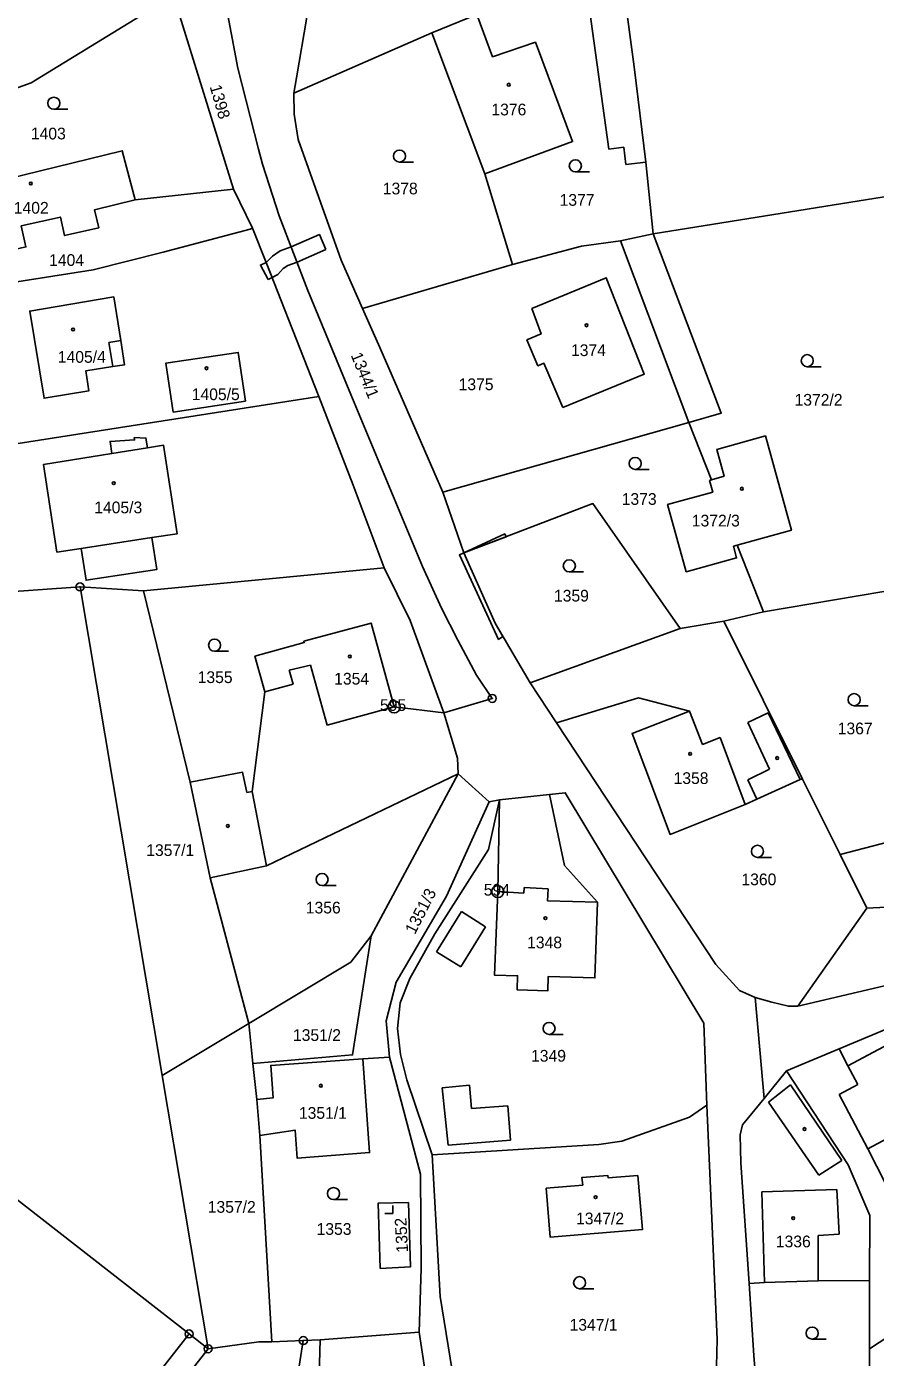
# Model space of a CAD drawing. Extents: x -587171 to -555306, y -1167727 to -1074732.
# Drawn here: x -559852.9 to -559747.3, y -1076385.1 to -1076219.5 of the extents above; entities that cross this region are included whole.
import ezdxf

# ---------------------------------------------------------------- set-up
doc = ezdxf.new("R2010")
doc.units = 0
for name, color, linetype in [('Hranice parcel', 7, 'Continuous'), ('Parcelní čísla', 7, 'Continuous'), ('Vnitřní kresba', 7, 'Continuous'), ('Věcná břemena k části', 7, 'Continuous'), ('Značky bodu BP', 7, 'Continuous'), ('Značky budov', 7, 'Continuous'), ('Značky kultur', 7, 'Continuous')]:
    doc.layers.add(name, color=color, linetype=linetype)

msp = doc.modelspace()

# ---------------------------------------------------------------- linework, layer by layer
at = {"layer": 'Hranice parcel'}
for p, q in [((-559834.6, -1076215.6), (-559827.15, -1076239.74)), ((-559796.86, -1076218), (-559802.48, -1076220.25)), ((-559802.48, -1076220.25), (-559819.62, -1076227.79)), ((-559802.48, -1076220.25), (-559795.86, -1076237.82)), ((-559795.86, -1076237.82), (-559792.44, -1076249.08)), ((-559839.38, -1076241.05), (-559827.15, -1076239.74)), ((-559827.15, -1076239.74), (-559824.78, -1076244.58)), ((-559746.19, -1076240.66), (-559774.92, -1076245.29)), ((-559792.44, -1076249.08), (-559811.08, -1076254.57)), ((-559917.53, -1076281.27), (-559816.53, -1076265.53)), ((-559770.49, -1076268.74), (-559801.09, -1076277.4)), ((-559767.68, -1076275.89), (-559770.49, -1076268.74)), ((-559801.09, -1076277.4), (-559798.5, -1076284.98)), ((-559761.21, -1076292.32), (-559764.48, -1076284.02)), ((-559808.4, -1076286.82), (-559838.33, -1076289.68)), ((-559838.33, -1076289.68), (-559846.23, -1076289.21)), ((-559836.01, -1076350.01), (-559846.23, -1076289.21)), ((-559838.33, -1076289.68), (-559832.53, -1076313.51)), ((-559742.81, -1076289.2), (-559761.21, -1076292.32)), ((-559766.15, -1076293.47), (-559771.58, -1076294.37)), ((-559761.21, -1076292.32), (-559766.15, -1076293.47)), ((-559756.34, -1076313.12), (-559766.15, -1076293.47)), ((-559771.58, -1076294.37), (-559790.22, -1076301.15)), ((-559790.22, -1076301.15), (-559786.94, -1076306.13)), ((-559810.01, -1076332.61), (-559799.17, -1076312.48)), ((-559799.17, -1076312.48), (-559795.34, -1076315.97)), ((-559751.67, -1076322.49), (-559756.34, -1076313.12)), ((-559832.53, -1076313.51), (-559830.02, -1076325.39)), ((-559787.84, -1076315.03), (-559794.04, -1076315.72)), ((-559795.34, -1076315.97), (-559794.04, -1076315.72)), ((-559732.13, -1076317.38), (-559751.67, -1076322.49)), ((-559748.34, -1076329.2), (-559751.67, -1076322.49)), ((-559830.02, -1076325.39), (-559825.24, -1076343.53)), ((-559725.3, -1076327.83), (-559748.34, -1076329.2)), ((-559756.94, -1076341.36), (-559748.34, -1076329.2)), ((-559762.25, -1076340.3), (-559761.13, -1076352.85)), ((-559836.01, -1076350.01), (-559825.24, -1076343.53)), ((-559824.71, -1076348.5), (-559825.24, -1076343.53)), ((-559807.72, -1076347.73), (-559811.03, -1076347.93)), ((-559751.79, -1076346.69), (-559758.34, -1076349.44)), ((-559824.24, -1076353), (-559824.71, -1076348.5)), ((-559758.34, -1076349.44), (-559761.13, -1076352.85)), ((-559830.29, -1076384), (-559836.01, -1076350.01)), ((-559823.85, -1076357.47), (-559824.24, -1076353)), ((-559823.85, -1076357.47), (-559822.35, -1076383.15)), ((-559748.01, -1076375.52), (-559748.02, -1076384.02)), ((-559832.66, -1076382.16), (-559859.22, -1076415.94)), ((-559832.66, -1076382.16), (-559830.29, -1076384)), ((-559824.03, -1076417.57), (-559818.45, -1076382.98)), ((-559822.35, -1076383.15), (-559818.45, -1076382.98)), ((-559818.45, -1076382.98), (-559816.37, -1076382.89)), ((-559816.37, -1076382.89), (-559817.26, -1076419.52)), ((-559816.37, -1076382.89), (-559804.04, -1076381.95)), ((-559850.66, -1076409.89), (-559830.29, -1076384)), ((-559748.02, -1076384.02), (-559748.03, -1076392.42))]:
    msp.add_line(p, q, dxfattribs=at)
for points in [[(-559800.97, -1076304.86), (-559794.95, -1076303.08), (-559796.9, -1076300.21), (-559799.24, -1076295.84), (-559801.24, -1076291.85), (-559803.62, -1076286.68), (-559812.53, -1076265.28), (-559817.89, -1076252.34), (-559821.44, -1076243.02), (-559823.53, -1076236.61), (-559824.03, -1076234.73), (-559826.59, -1076224.66), (-559827.84, -1076218.06), (-559841.06, -1076192.8), (-559849.12, -1076174.99), (-559857.26, -1076167.36)], [(-559774.92, -1076245.29), (-559775.85, -1076236.38), (-559777.29, -1076224.48), (-559778.44, -1076215.79), (-559778.91, -1076212.75), (-559779.06, -1076211.43)], [(-559869.77, -1076226.68), (-559859.12, -1076228.2), (-559855.88, -1076227.77), (-559852.31, -1076226.49), (-559838.82, -1076218.24), (-559834.6, -1076215.6)], [(-559818.01, -1076218.3), (-559819.29, -1076225.85), (-559819.62, -1076227.79)], [(-559795.86, -1076237.82), (-559784.95, -1076233.8), (-559789.57, -1076221.43), (-559794.91, -1076223.25), (-559796.86, -1076218)], [(-559819.62, -1076227.79), (-559819.6, -1076230.38), (-559819.11, -1076233.54), (-559813.74, -1076248.54), (-559811.08, -1076254.57)], [(-559839.38, -1076241.05), (-559840.97, -1076234.95), (-559865.74, -1076240.99)], [(-559865.74, -1076240.99), (-559864.38, -1076246.84), (-559857.63, -1076245.05), (-559857, -1076247.84), (-559852.95, -1076246.91), (-559853.54, -1076244.3), (-559848.67, -1076243.2), (-559848.15, -1076245.5), (-559843.9, -1076244.53), (-559844.41, -1076242.28), (-559839.38, -1076241.05)], [(-559893.84, -1076256.62), (-559892.61, -1076256.66), (-559878.73, -1076257.12), (-559856.24, -1076251.59), (-559844.61, -1076249.76), (-559835.87, -1076247.54), (-559825.05, -1076244.68), (-559824.78, -1076244.58)], [(-559824.78, -1076244.58), (-559823.08, -1076248.83), (-559816.53, -1076265.53)], [(-559774.92, -1076245.29), (-559778.98, -1076246.13), (-559783.85, -1076246.81), (-559792.44, -1076249.08)], [(-559770.49, -1076268.74), (-559766.45, -1076267.6), (-559774.92, -1076245.29)], [(-559786.16, -1076266.88), (-559776.04, -1076262.72), (-559780.76, -1076250.75), (-559790.02, -1076254.58), (-559788.87, -1076257.73), (-559790.63, -1076258.47), (-559789.26, -1076261.7), (-559788.53, -1076261.39), (-559786.16, -1076266.88)], [(-559841.16, -1076258.56), (-559840.68, -1076261.56), (-559842.15, -1076261.78), (-559845.51, -1076262.33), (-559845.12, -1076264.81), (-559850.7, -1076265.74), (-559852.48, -1076254.88), (-559842.03, -1076253.12), (-559841.16, -1076258.56)], [(-559811.08, -1076254.57), (-559808.95, -1076259.43), (-559801.09, -1076277.4)], [(-559834.65, -1076267.45), (-559835.56, -1076261.39), (-559826.55, -1076260.04), (-559825.65, -1076266.08), (-559834.65, -1076267.45)], [(-559816.53, -1076265.53), (-559812.23, -1076276.55), (-559808.4, -1076286.82)], [(-559767.68, -1076275.89), (-559766.1, -1076275.44), (-559767.03, -1076272.1), (-559760.97, -1076270.42), (-559757.74, -1076282.14), (-559764.48, -1076284.02)], [(-559849.1, -1076284.9), (-559850.79, -1076273.98), (-559842.25, -1076272.6), (-559842.49, -1076271.11), (-559839.44, -1076270.92), (-559839.49, -1076270.62), (-559838.04, -1076270.69), (-559837.85, -1076271.89), (-559835.86, -1076271.56), (-559834.16, -1076282.61), (-559837.28, -1076283.08), (-559836.67, -1076287.04), (-559845.47, -1076288.38), (-559846.07, -1076284.43), (-559849.1, -1076284.9)], [(-559764.48, -1076284.02), (-559764.93, -1076284.15), (-559764.56, -1076285.6), (-559770.81, -1076287.33), (-559773.14, -1076278.97), (-559767.51, -1076277.41), (-559767.91, -1076275.96), (-559767.68, -1076275.89)], [(-559771.58, -1076294.37), (-559782.43, -1076278.85), (-559798.5, -1076284.98)], [(-559798.5, -1076284.98), (-559794.59, -1076293.71), (-559790.22, -1076301.15)], [(-559800.97, -1076304.86), (-559805.16, -1076293.4), (-559808.4, -1076286.82)], [(-559846.23, -1076289.21), (-559860.89, -1076290.23), (-559893.42, -1076293.34)], [(-559893.42, -1076293.34), (-559875.13, -1076349.05), (-559832.66, -1076382.16)], [(-559800.97, -1076304.86), (-559807.14, -1076304.14), (-559809.99, -1076293.71), (-559818.38, -1076295.96), (-559818.33, -1076296.13), (-559824.48, -1076297.83), (-559823.22, -1076302.26), (-559824.82, -1076314.65), (-559825.46, -1076314.77), (-559826, -1076312.27), (-559832.53, -1076313.51)], [(-559786.94, -1076306.13), (-559776.75, -1076303.02), (-559770.42, -1076304.66), (-559777.56, -1076307.45), (-559772.82, -1076320.01), (-559763.47, -1076316.27), (-559762.03, -1076315.61), (-559756.65, -1076313.18), (-559756.34, -1076313.12)], [(-559799.17, -1076312.48), (-559799.26, -1076310.52), (-559800.97, -1076304.86)], [(-559786.94, -1076306.13), (-559767.15, -1076336.2), (-559764.2, -1076339.43), (-559762.25, -1076340.3)], [(-559830.02, -1076325.39), (-559823.02, -1076323.91), (-559799.17, -1076312.48)], [(-559794.04, -1076315.72), (-559794.26, -1076327.12), (-559794.65, -1076337.52), (-559791.8, -1076337.59), (-559791.84, -1076339.35), (-559788.03, -1076339.46), (-559787.98, -1076337.7), (-559782.17, -1076337.85), (-559781.86, -1076328.43), (-559785.98, -1076323.86), (-559787.84, -1076315.03)], [(-559768.25, -1076353.7), (-559768.62, -1076343.5), (-559785.86, -1076314.81), (-559787.84, -1076315.03)], [(-559795.34, -1076315.97), (-559800.62, -1076327.69), (-559806.89, -1076338.39), (-559808.15, -1076343.22), (-559807.72, -1076347.73)], [(-559794.04, -1076315.72), (-559795.41, -1076321.87), (-559802.07, -1076332.38), (-559805.2, -1076337.92), (-559806.4, -1076340.98), (-559806.74, -1076344.16), (-559806.38, -1076347.37), (-559805.57, -1076350.54), (-559802.41, -1076359.86)], [(-559825.24, -1076343.53), (-559812.56, -1076335.9), (-559810.01, -1076332.61)], [(-559824.71, -1076348.5), (-559812.33, -1076347.43), (-559810.01, -1076332.61)], [(-559702.24, -1076345.64), (-559726.29, -1076337.65), (-559734.22, -1076336.48), (-559742.09, -1076337.88), (-559756.94, -1076341.36)], [(-559756.94, -1076341.36), (-559758.11, -1076341.38), (-559760.15, -1076340.87), (-559762.25, -1076340.3)], [(-559738.33, -1076341.52), (-559741.88, -1076342.53), (-559751.79, -1076346.69)], [(-559748.02, -1076384.02), (-559742.01, -1076380.08), (-559732.34, -1076376.02), (-559734.46, -1076370.82), (-559734.83, -1076367.76), (-559740.49, -1076370.33), (-559742.68, -1076370.04), (-559748.24, -1076359.12), (-559738.45, -1076353.89), (-559743.09, -1076344.75), (-559750.71, -1076348.8), (-559751.79, -1076346.69)], [(-559811.03, -1076347.93), (-559822.5, -1076348.74), (-559822.22, -1076352.78), (-559824.24, -1076353)], [(-559811.03, -1076347.93), (-559810.2, -1076359.59), (-559819.22, -1076360.27), (-559819.46, -1076356.82), (-559823.85, -1076357.47)], [(-559804.04, -1076381.95), (-559803.79, -1076374), (-559803.88, -1076362.26), (-559807.72, -1076347.73)], [(-559758.34, -1076349.44), (-559750.69, -1076361.1), (-559747.99, -1076367.42), (-559748.01, -1076375.52)], [(-559761.13, -1076352.85), (-559763.8, -1076356.16), (-559764.1, -1076357.4), (-559764.02, -1076360.87), (-559763, -1076375.89)], [(-559802.41, -1076359.86), (-559781.68, -1076358.6), (-559778.81, -1076358.17), (-559770.41, -1076355.2), (-559768.25, -1076353.7)], [(-559767.04, -1076386.16), (-559766.95, -1076382.85), (-559768.25, -1076353.7)], [(-559802.41, -1076359.86), (-559801.41, -1076377.51), (-559799.2, -1076391.32)], [(-559776.82, -1076362.43), (-559776.27, -1076369.17), (-559787.75, -1076370.1), (-559788.24, -1076364.02), (-559783.68, -1076363.64), (-559783.8, -1076362.69), (-559780.58, -1076362.43), (-559780.53, -1076362.72), (-559776.82, -1076362.43)], [(-559805.35, -1076365.82), (-559809.14, -1076365.9), (-559808.89, -1076374), (-559805.1, -1076373.8), (-559805.35, -1076365.82)], [(-559763, -1076375.89), (-559761.06, -1076375.76), (-559754.39, -1076375.56), (-559748.01, -1076375.52)], [(-559763, -1076375.89), (-559762.39, -1076384.85), (-559761.67, -1076393.83)], [(-559789.16, -1076422.56), (-559789.8, -1076418.9), (-559790.62, -1076415.63), (-559800.04, -1076398.01), (-559802.57, -1076391.51), (-559804.04, -1076381.95)], [(-559830.29, -1076384), (-559824, -1076383.13), (-559822.35, -1076383.15)]]:
    msp.add_lwpolyline(points, dxfattribs=at)
at = {"layer": 'Vnitřní kresba'}
for p, q in [((-559782.85, -1076217.35), (-559780.45, -1076234.76)), ((-559780.45, -1076234.76), (-559778.56, -1076234.5)), ((-559778.56, -1076234.5), (-559778.31, -1076236.65)), ((-559778.31, -1076236.65), (-559775.85, -1076236.38)), ((-559778.98, -1076246.13), (-559770.49, -1076268.74)), ((-559841.16, -1076258.56), (-559842.63, -1076258.79)), ((-559842.63, -1076258.79), (-559842.15, -1076261.78)), ((-559842.25, -1076272.6), (-559837.85, -1076271.89)), ((-559846.07, -1076284.43), (-559837.28, -1076283.08)), ((-559820.2, -1076299.58), (-559817.55, -1076298.94)), ((-559819.72, -1076301.31), (-559820.2, -1076299.58)), ((-559817.55, -1076298.94), (-559815.49, -1076306.41)), ((-559823.22, -1076302.26), (-559819.72, -1076301.31)), ((-559815.49, -1076306.41), (-559807.14, -1076304.14)), ((-559768.8, -1076308.82), (-559770.42, -1076304.66)), ((-559763.14, -1076306.09), (-559760.64, -1076304.89)), ((-559760.64, -1076304.89), (-559756.65, -1076313.18)), ((-559760.45, -1076311.9), (-559763.14, -1076306.09)), ((-559766.6, -1076307.94), (-559768.8, -1076308.82)), ((-559763.47, -1076316.27), (-559766.6, -1076307.94)), ((-559763.17, -1076313.22), (-559760.45, -1076311.9)), ((-559762.03, -1076315.61), (-559763.17, -1076313.22)), ((-559823.02, -1076323.91), (-559824.82, -1076314.65)), ((-559790.98, -1076326.63), (-559791.01, -1076327.31)), ((-559788.01, -1076326.76), (-559790.98, -1076326.63)), ((-559791.01, -1076327.31), (-559794.26, -1076327.12)), ((-559788.07, -1076328.27), (-559788.01, -1076326.76)), ((-559781.86, -1076328.43), (-559788.07, -1076328.27)), ((-559801.88, -1076334.62), (-559798.79, -1076329.6)), ((-559798.79, -1076329.6), (-559795.8, -1076331.51)), ((-559795.8, -1076331.51), (-559798.87, -1076336.47)), ((-559798.87, -1076336.47), (-559801.88, -1076334.62)), ((-559749.48, -1076351.13), (-559750.71, -1076348.8)), ((-559801.18, -1076351.53), (-559797.78, -1076351.21)), ((-559800.45, -1076358.65), (-559801.18, -1076351.53)), ((-559797.78, -1076351.21), (-559797.53, -1076354.11)), ((-559760.58, -1076353.33), (-559757.86, -1076351.18)), ((-559757.86, -1076351.18), (-559751.47, -1076360.58)), ((-559751.78, -1076352.38), (-559749.48, -1076351.13)), ((-559748.24, -1076359.12), (-559751.78, -1076352.38)), ((-559797.53, -1076354.11), (-559793.01, -1076353.76)), ((-559793.01, -1076353.76), (-559792.66, -1076358.06)), ((-559754.33, -1076362.4), (-559760.58, -1076353.33)), ((-559792.66, -1076358.06), (-559800.45, -1076358.65)), ((-559751.47, -1076360.58), (-559754.33, -1076362.4)), ((-559761.42, -1076364.49), (-559752.1, -1076364.18)), ((-559761.06, -1076375.76), (-559761.42, -1076364.49)), ((-559752.1, -1076364.18), (-559751.79, -1076369.76)), ((-559751.79, -1076369.76), (-559754.41, -1076369.91)), ((-559754.41, -1076369.91), (-559754.39, -1076375.56))]:
    msp.add_line(p, q, dxfattribs=at)
at = {"layer": 'Věcná břemena k části'}
for points in [[(-559815.63, -1076247.24), (-559816.45, -1076245.38), (-559819.96, -1076246.9), (-559821.33, -1076247.41), (-559822.27, -1076248.05), (-559823.08, -1076248.83), (-559822.34, -1076250.71), (-559821.64, -1076250.33), (-559820.95, -1076249.61), (-559820.39, -1076249.23), (-559819.23, -1076248.82)], [(-559822.83, -1076250.97), (-559822.34, -1076250.71), (-559823.08, -1076248.83), (-559823.79, -1076249.17)], [(-559793.21, -1076282.96), (-559793.39, -1076282.62), (-559798.5, -1076284.98)], [(-559793.61, -1076295.37), (-559794.59, -1076293.71), (-559798.5, -1076284.98), (-559799.04, -1076285.23), (-559794.15, -1076295.74)]]:
    msp.add_lwpolyline(points, close=True, dxfattribs=at)
at = {"layer": 'Značky bodu BP'}
for centre, radius in [((-559846.23, -1076289.21), 0.5), ((-559846.23, -1076289.21), 0.0303), ((-559807.14, -1076304.14), 0.75), ((-559794.95, -1076303.08), 0.5), ((-559794.95, -1076303.08), 0.0303), ((-559807.14, -1076304.14), 0.03), ((-559794.26, -1076327.12), 0.75), ((-559794.26, -1076327.12), 0.03), ((-559832.66, -1076382.16), 0.5), ((-559832.66, -1076382.16), 0.0303), ((-559818.45, -1076382.98), 0.5), ((-559818.45, -1076382.98), 0.0303), ((-559830.29, -1076384), 0.5), ((-559830.29, -1076384), 0.0303)]:
    msp.add_circle(centre, radius, dxfattribs=at)
at = {"layer": 'Značky budov'}
for centre in [(-559792.9, -1076226.72), (-559852.35, -1076239.01), (-559847.1, -1076257.19), (-559783.22, -1076256.66), (-559830.49, -1076262.01), (-559842.04, -1076276.31), (-559763.89, -1076276.99), (-559812.66, -1076297.86), (-559770.33, -1076309.97), (-559759.5, -1076310.5), (-559827.84, -1076318.95), (-559788.34, -1076330.43), (-559816.27, -1076351.27), (-559756.1, -1076356.66), (-559782.09, -1076365.14), (-559757.51, -1076367.75)]:
    msp.add_circle(centre, 0.175, dxfattribs=at)
at = {"layer": 'Značky kultur'}
for p, q in [((-559849.48, -1076229.78), (-559847.73, -1076229.78)), ((-559806.48, -1076236.35), (-559804.73, -1076236.35)), ((-559784.61, -1076237.57), (-559782.86, -1076237.57)), ((-559755.76, -1076261.81), (-559754.01, -1076261.81)), ((-559777.17, -1076274.59), (-559775.42, -1076274.59)), ((-559785.36, -1076287.34), (-559783.61, -1076287.34)), ((-559829.49, -1076297.21), (-559827.74, -1076297.21)), ((-559749.92, -1076303.99), (-559748.17, -1076303.99)), ((-559761.96, -1076322.86), (-559760.21, -1076322.86)), ((-559816.12, -1076326.36), (-559814.37, -1076326.36)), ((-559787.88, -1076344.89), (-559786.13, -1076344.89)), ((-559814.69, -1076365.44), (-559812.94, -1076365.44)), ((-559807.31, -1076367.19), (-559807.31, -1076366.19)), ((-559808.31, -1076367.19), (-559807.31, -1076367.19)), ((-559784.08, -1076376.53), (-559782.33, -1076376.53)), ((-559755.15, -1076382.8), (-559753.4, -1076382.8))]:
    msp.add_line(p, q, dxfattribs=at)
for centre in [(-559849.48, -1076229.03), (-559806.48, -1076235.6), (-559784.61, -1076236.82), (-559755.76, -1076261.06), (-559777.17, -1076273.84), (-559785.36, -1076286.59), (-559829.49, -1076296.46), (-559749.92, -1076303.24), (-559761.96, -1076322.11), (-559816.12, -1076325.61), (-559787.88, -1076344.14), (-559814.69, -1076364.69), (-559784.08, -1076375.78), (-559755.15, -1076382.05)]:
    msp.add_circle(centre, 0.75, dxfattribs=at)

# ---------------------------------------------------------------- texts
at = {"layer": 'Parcelní čísla'}
for s, rotation, p in [('1398', 286, (-559830.11, -1076226.95)), ('1344/1', 292, (-559812.57, -1076260.37)), ('1351/3', 63, (-559804.57, -1076332.53)), ('1352', 93, (-559805.41, -1076372))]:
    msp.add_text(s, height=1.46, rotation=rotation, dxfattribs=at).set_placement(p)
for s, p in [('1376', (-559795.05, -1076230.54)), ('1403', (-559852.34, -1076233.53)), ('1378', (-559808.56, -1076240.37)), ('1377', (-559786.57, -1076241.79)), ('1402', (-559854.47, -1076242.77)), ('1404', (-559850.07, -1076249.27)), ('1405/4', (-559848.99, -1076261.32)), ('1374', (-559785.15, -1076260.49)), ('1375', (-559799.13, -1076264.73)), ('1405/5', (-559832.33, -1076265.97)), ('1372/2', (-559757.34, -1076266.66)), ('1405/3', (-559844.46, -1076280.05)), ('1373', (-559778.84, -1076279)), ('1372/3', (-559770.12, -1076281.69)), ('1359', (-559787.27, -1076291.03)), ('1355', (-559831.59, -1076301.17)), ('1354', (-559814.61, -1076301.36)), ('1367', (-559751.97, -1076307.55)), ('1358', (-559772.39, -1076313.73)), ('1357/1', (-559837.99, -1076322.69)), ('1360', (-559763.95, -1076326.33)), ('1356', (-559818.14, -1076329.84)), ('1348', (-559790.61, -1076334.18)), ('1351/2', (-559819.74, -1076345.7)), ('1349', (-559790.12, -1076348.28)), ('1351/1', (-559819, -1076355.39)), ('1357/2', (-559830.34, -1076367.08)), ('1347/2', (-559784.52, -1076368.52)), ('1353', (-559816.8, -1076369.83)), ('1336', (-559759.67, -1076371.38)), ('1347/1', (-559785.33, -1076381.75))]:
    msp.add_text(s, height=1.46, dxfattribs=at).set_placement(p)
at = {"layer": 'Značky bodu BP'}
for s, p in [('595', (-559808.91, -1076304.64)), ('594', (-559796, -1076327.62))]:
    msp.add_text(s, height=1.46, dxfattribs=at).set_placement(p)

doc.saveas('drawing.dxf')
